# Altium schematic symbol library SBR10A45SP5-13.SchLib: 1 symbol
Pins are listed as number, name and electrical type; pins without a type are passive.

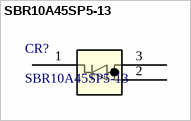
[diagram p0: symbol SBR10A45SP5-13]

## SBR10A45SP5-13
designator CR?
No Description Available; Manufacturer_Name: Diodes Inc
footprint POWERDI5_DIO
pins: 1 CATHODE, 2 ANODE, 3 ANODE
